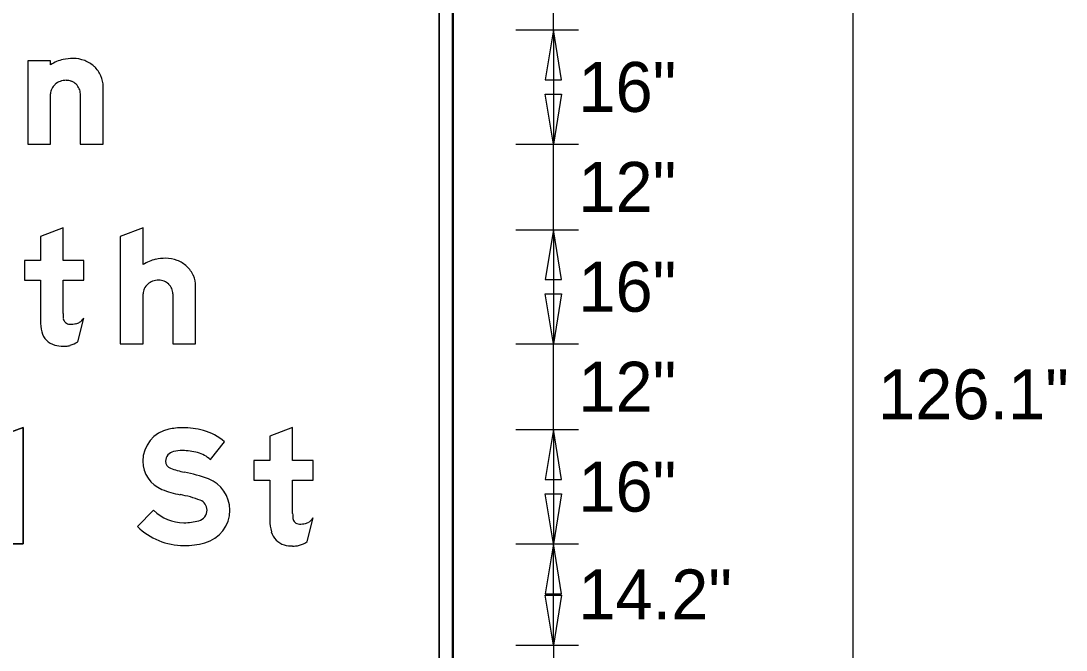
# Model space of a CAD drawing. Extents: x 2149961 to 2150220, y 145114 to 145240.
# Drawn here: x 2149993.88 to 2150006.08, y 145219.03 to 145226.37 of the extents above; entities that cross this region are included whole.
import ezdxf

# ---------------------------------------------------------------- set-up
doc = ezdxf.new("R2010")
doc.units = 0
for name, color, linetype in [('GSBWFILL', 7, 'Continuous'), ('GSCOLORFILL', 7, 'Continuous'), ('GSDIMS', 7, 'Continuous'), ('GSOUTLINE', 7, 'Continuous')]:
    doc.layers.add(name, color=color, linetype=linetype)

msp = doc.modelspace()

# ---------------------------------------------------------------- linework, layer by layer
at = {"layer": 'GSBWFILL'}
for p, q in [((2149998.763, 145232.262), (2149998.763, 145217.762)), ((2149998.93, 145217.762), (2149998.93, 145232.262)), ((2149994.572, 145225.522), (2149994.572, 145224.937)), ((2149994.542, 145222.628), (2149994.612, 145222.904)), ((2149997.222, 145220.295), (2149997.292, 145220.571))]:
    msp.add_line(p, q, dxfattribs=at)
for points in [[(2149994.226, 145225.862), (2149994.226, 145225.91), (2149993.959, 145225.91), (2149993.959, 145224.937), (2149994.226, 145224.937), (2149994.226, 145225.522)], [(2149994.572, 145224.937), (2149994.839, 145224.937), (2149994.839, 145225.609)], [(2149994.372, 145222.957), (2149994.372, 145223.347), (2149994.612, 145223.347), (2149994.612, 145223.577), (2149994.372, 145223.577), (2149994.372, 145223.96), (2149994.106, 145223.859), (2149994.106, 145223.577), (2149993.919, 145223.577), (2149993.919, 145223.347), (2149994.106, 145223.347), (2149994.106, 145222.876)], [(2149995.306, 145223.529), (2149995.306, 145223.96), (2149995.039, 145223.857), (2149995.039, 145222.604), (2149995.306, 145222.604), (2149995.306, 145223.188)], [(2149995.652, 145223.188), (2149995.652, 145222.604), (2149995.919, 145222.604), (2149995.919, 145223.276)], [(2149993.639, 145220.302), (2149993.639, 145220.27), (2149993.906, 145220.27), (2149993.906, 145221.627), (2149993.639, 145221.529), (2149993.639, 145221.212)], [(2149997.052, 145220.624), (2149997.052, 145221.014), (2149997.292, 145221.014), (2149997.292, 145221.244), (2149997.052, 145221.244), (2149997.052, 145221.627), (2149996.786, 145221.526), (2149996.786, 145221.244), (2149996.599, 145221.244), (2149996.599, 145221.014), (2149996.786, 145221.014), (2149996.786, 145220.543)], [(2149996.092, 145221.252), (2149996.257, 145221.462)], [(2149995.427, 145220.662), (2149995.239, 145220.473)]]:
    msp.add_lwpolyline(points, dxfattribs=at)
for centre, radius, start, end in [((2149994.483, 145225.457), 0.48, 103.4695, 122.4943), ((2149994.488, 145225.403), 0.533, 90, 102.6043), ((2149994.488, 145225.561), 0.375, 68.8636, 90), ((2149994.497, 145225.585), 0.35, 46.975, 68.8636), ((2149994.511, 145225.6), 0.33, 23.9317, 46.975), ((2149994.399, 145225.496), 0.183, 109.8074, 131.0076), ((2149994.408, 145225.471), 0.21, 90, 109.8074), ((2149994.408, 145225.512), 0.168, 68.0808, 90), ((2149994.41, 145225.517), 0.164, 45.8298, 68.0808), ((2149994.533, 145225.609), 0.306, 0, 23.9317), ((2149994.364, 145225.522), 0.139, 154.5283, 180), ((2149994.386, 145225.511), 0.162, 131.0076, 154.5283), ((2149994.413, 145225.52), 0.159, 23.0928, 45.8298), ((2149994.418, 145225.522), 0.155, 0, 23.0928), ((2149995.563, 145223.124), 0.48, 103.4695, 122.4943), ((2149995.568, 145223.07), 0.533, 90, 102.6043), ((2149995.568, 145223.228), 0.375, 68.8636, 90), ((2149995.577, 145223.252), 0.35, 46.975, 68.8636), ((2149995.591, 145223.266), 0.33, 23.9317, 46.975), ((2149995.479, 145223.162), 0.183, 109.8074, 131.0076), ((2149995.488, 145223.137), 0.21, 90, 109.8074), ((2149995.488, 145223.179), 0.168, 68.0808, 90), ((2149995.49, 145223.183), 0.164, 45.8298, 68.0808), ((2149995.613, 145223.276), 0.306, 0, 23.9317), ((2149995.444, 145223.188), 0.139, 154.5283, 180), ((2149995.466, 145223.178), 0.162, 131.0076, 154.5283), ((2149995.493, 145223.186), 0.159, 23.0928, 45.8298), ((2149995.498, 145223.188), 0.155, 0, 23.0928)]:
    msp.add_arc(centre, radius, start, end, dxfattribs=at)
for centre, major_axis, ratio, start_param, end_param in [((2149996.041, 145222.957), (0, 1.669), 0.99999, 1.570796, 1.606005), ((2149994.623, 145222.876), (0, 0.517), 0.99999, 1.570796, 1.830698), ((2149994.449, 145222.911), (0, 0.0767), 0.99999, 1.74085, 2.407828), ((2149994.451, 145222.914), (0, 0.0803), 0.99999, 2.407828, 3.141593), ((2149994.451, 145223.255), (0, 0.421), 0.99999, 3.141593, 3.310762), ((2149994.505, 145222.938), (0, 0.1), 0.99999, 3.310762, 3.756278), ((2149994.437, 145223.035), (0, 0.219), 0.99999, 3.756278, 4.071638), ((2149994.332, 145222.799), (0, 0.217), 0.99999, 1.830698, 2.869526), ((2149994.372, 145222.942), (0, 0.365), 0.99999, 2.869526, 3.141593), ((2149994.364, 145222.891), (0, 0.317), 0.99999, 3.427755, 3.738844), ((2149994.372, 145223.103), (0, 0.526), 0.99999, 3.141593, 3.205734), ((2149994.392, 145222.794), (0, 0.217), 0.99999, 3.205734, 3.427755), ((2149995.765, 145220.839), (0, 0.785), 0.999996, 0, 0.202758), ((2149995.765, 145220.661), (0, 0.963), 0.999996, 6.026234, 6.283185), ((2149995.684, 145221.234), (0, 0.382), 0.999996, 0.202758, 1.570796), ((2149995.855, 145221.001), (0, 0.611), 0.999996, 5.565152, 6.026234), ((2149995.684, 145221.234), (0, 0.115), 0.999996, 0.202758, 1.570796), ((2149995.765, 145220.839), (0, 0.519), 0.999996, 0, 0.202758), ((2149995.765, 145220.661), (0, 0.697), 0.999996, 6.026234, 6.283185), ((2149995.855, 145221.001), (0, 0.345), 0.999996, 5.523837, 6.026234), ((2149995.656, 145221.234), (0, 0.354), 0.999996, 1.570796, 2.761249), ((2149995.656, 145221.234), (0, 0.0872), 0.999996, 1.570796, 2.761249), ((2149995.947, 145221.961), (0, 0.87), 0.999996, 2.761249, 2.95744), ((2149995.49, 145219.51), (0, 1.623), 0.999996, 5.918637, 6.099033), ((2149995.93, 145220.664), (0, 0.388), 0.999996, 4.712389, 5.918637), ((2149995.947, 145221.961), (0, 1.137), 0.999996, 2.761249, 2.95744), ((2149995.49, 145219.51), (0, 1.357), 0.999996, 5.918637, 6.099033), ((2149995.93, 145220.664), (0, 0.122), 0.999996, 4.712389, 5.918637), ((2149995.782, 145221.02), (0, 0.504), 0.999996, 2.360607, 3.141593), ((2149995.923, 145220.664), (0, 0.129), 0.999996, 3.401517, 4.712389), ((2149995.923, 145220.664), (0, 0.396), 0.999996, 3.401517, 4.712389), ((2149995.782, 145221.194), (0, 0.678), 0.999996, 3.141593, 3.401517), ((2149997.303, 145220.543), (0, 0.517), 0.999994, 1.570796, 1.830698), ((2149998.721, 145220.624), (0, 1.669), 0.999994, 1.570796, 1.606005), ((2149997.129, 145220.578), (0, 0.0767), 0.999994, 1.74085, 2.407828), ((2149997.131, 145220.58), (0, 0.0803), 0.999994, 2.407828, 3.141593), ((2149997.185, 145220.605), (0, 0.1), 0.999994, 3.310762, 3.756278), ((2149997.117, 145220.702), (0, 0.219), 0.999994, 3.756278, 4.071638), ((2149995.782, 145221.02), (0, 0.771), 0.999996, 2.360607, 3.141593), ((2149997.012, 145220.466), (0, 0.217), 0.999994, 1.830698, 2.869526), ((2149997.131, 145220.921), (0, 0.421), 0.999994, 3.141593, 3.310762), ((2149995.782, 145221.194), (0, 0.945), 0.999996, 3.141593, 3.401517), ((2149997.044, 145220.557), (0, 0.317), 0.999994, 3.427755, 3.738844), ((2149997.052, 145220.609), (0, 0.365), 0.999994, 2.869526, 3.141593), ((2149997.052, 145220.769), (0, 0.526), 0.999994, 3.141593, 3.205734), ((2149997.072, 145220.461), (0, 0.217), 0.999994, 3.205734, 3.427755)]:
    msp.add_ellipse(centre, major_axis=major_axis, ratio=ratio, start_param=start_param, end_param=end_param, dxfattribs=at)
at = {"layer": 'GSCOLORFILL'}
for p, q in [((2149998.763, 145232.262), (2149998.763, 145217.762)), ((2149998.913, 145232.262), (2149998.913, 145217.762)), ((2149998.93, 145217.762), (2149998.93, 145232.262)), ((2149998.93, 145217.762), (2149998.93, 145232.262)), ((2149998.93, 145217.762), (2149998.93, 145232.262)), ((2149994.572, 145225.522), (2149994.572, 145224.937)), ((2149994.542, 145222.628), (2149994.612, 145222.904)), ((2149997.222, 145220.295), (2149997.292, 145220.571))]:
    msp.add_line(p, q, dxfattribs=at)
for points in [[(2149994.226, 145225.862), (2149994.226, 145225.91), (2149993.959, 145225.91), (2149993.959, 145224.937), (2149994.226, 145224.937), (2149994.226, 145225.522)], [(2149994.572, 145224.937), (2149994.839, 145224.937), (2149994.839, 145225.609)], [(2149994.372, 145222.957), (2149994.372, 145223.347), (2149994.612, 145223.347), (2149994.612, 145223.577), (2149994.372, 145223.577), (2149994.372, 145223.96), (2149994.106, 145223.859), (2149994.106, 145223.577), (2149993.919, 145223.577), (2149993.919, 145223.347), (2149994.106, 145223.347), (2149994.106, 145222.876)], [(2149995.306, 145223.529), (2149995.306, 145223.96), (2149995.039, 145223.857), (2149995.039, 145222.604), (2149995.306, 145222.604), (2149995.306, 145223.188)], [(2149995.652, 145223.188), (2149995.652, 145222.604), (2149995.919, 145222.604), (2149995.919, 145223.276)], [(2149993.639, 145220.302), (2149993.639, 145220.27), (2149993.906, 145220.27), (2149993.906, 145221.627), (2149993.639, 145221.529), (2149993.639, 145221.212)], [(2149997.052, 145220.624), (2149997.052, 145221.014), (2149997.292, 145221.014), (2149997.292, 145221.244), (2149997.052, 145221.244), (2149997.052, 145221.627), (2149996.786, 145221.526), (2149996.786, 145221.244), (2149996.599, 145221.244), (2149996.599, 145221.014), (2149996.786, 145221.014), (2149996.786, 145220.543)], [(2149996.092, 145221.252), (2149996.257, 145221.462)], [(2149995.427, 145220.662), (2149995.239, 145220.473)]]:
    msp.add_lwpolyline(points, dxfattribs=at)
for centre, radius, start, end in [((2149994.483, 145225.457), 0.48, 103.4695, 122.4943), ((2149994.488, 145225.403), 0.533, 90, 102.6043), ((2149994.488, 145225.561), 0.375, 68.8636, 90), ((2149994.497, 145225.585), 0.35, 46.975, 68.8636), ((2149994.511, 145225.6), 0.33, 23.9317, 46.975), ((2149994.399, 145225.496), 0.183, 109.8074, 131.0076), ((2149994.408, 145225.471), 0.21, 90, 109.8074), ((2149994.408, 145225.512), 0.168, 68.0808, 90), ((2149994.41, 145225.517), 0.164, 45.8298, 68.0808), ((2149994.533, 145225.609), 0.306, 0, 23.9317), ((2149994.364, 145225.522), 0.139, 154.5283, 180), ((2149994.386, 145225.511), 0.162, 131.0076, 154.5283), ((2149994.413, 145225.52), 0.159, 23.0928, 45.8298), ((2149994.418, 145225.522), 0.155, 0, 23.0928), ((2149995.563, 145223.124), 0.48, 103.4695, 122.4943), ((2149995.568, 145223.07), 0.533, 90, 102.6043), ((2149995.568, 145223.228), 0.375, 68.8636, 90), ((2149995.577, 145223.252), 0.35, 46.975, 68.8636), ((2149995.591, 145223.266), 0.33, 23.9317, 46.975), ((2149995.479, 145223.162), 0.183, 109.8074, 131.0076), ((2149995.488, 145223.137), 0.21, 90, 109.8074), ((2149995.488, 145223.179), 0.168, 68.0808, 90), ((2149995.49, 145223.183), 0.164, 45.8298, 68.0808), ((2149995.613, 145223.276), 0.306, 0, 23.9317), ((2149995.444, 145223.188), 0.139, 154.5283, 180), ((2149995.466, 145223.178), 0.162, 131.0076, 154.5283), ((2149995.493, 145223.186), 0.159, 23.0928, 45.8298), ((2149995.498, 145223.188), 0.155, 0, 23.0928)]:
    msp.add_arc(centre, radius, start, end, dxfattribs=at)
for centre, major_axis, ratio, start_param, end_param in [((2149996.041, 145222.957), (0, 1.669), 0.99999, 1.570796, 1.606005), ((2149994.623, 145222.876), (0, 0.517), 0.99999, 1.570796, 1.830698), ((2149994.449, 145222.911), (0, 0.0767), 0.99999, 1.74085, 2.407828), ((2149994.451, 145222.914), (0, 0.0803), 0.99999, 2.407828, 3.141593), ((2149994.451, 145223.255), (0, 0.421), 0.99999, 3.141593, 3.310762), ((2149994.505, 145222.938), (0, 0.1), 0.99999, 3.310762, 3.756278), ((2149994.437, 145223.035), (0, 0.219), 0.99999, 3.756278, 4.071638), ((2149994.332, 145222.799), (0, 0.217), 0.99999, 1.830698, 2.869526), ((2149994.372, 145222.942), (0, 0.365), 0.99999, 2.869526, 3.141593), ((2149994.364, 145222.891), (0, 0.317), 0.99999, 3.427755, 3.738844), ((2149994.372, 145223.103), (0, 0.526), 0.99999, 3.141593, 3.205734), ((2149994.392, 145222.794), (0, 0.217), 0.99999, 3.205734, 3.427755), ((2149995.765, 145220.839), (0, 0.785), 0.999996, 0, 0.202758), ((2149995.765, 145220.661), (0, 0.963), 0.999996, 6.026234, 6.283185), ((2149995.684, 145221.234), (0, 0.382), 0.999996, 0.202758, 1.570796), ((2149995.855, 145221.001), (0, 0.611), 0.999996, 5.565152, 6.026234), ((2149995.684, 145221.234), (0, 0.115), 0.999996, 0.202758, 1.570796), ((2149995.765, 145220.839), (0, 0.519), 0.999996, 0, 0.202758), ((2149995.765, 145220.661), (0, 0.697), 0.999996, 6.026234, 6.283185), ((2149995.855, 145221.001), (0, 0.345), 0.999996, 5.523837, 6.026234), ((2149995.656, 145221.234), (0, 0.354), 0.999996, 1.570796, 2.761249), ((2149995.656, 145221.234), (0, 0.0872), 0.999996, 1.570796, 2.761249), ((2149995.947, 145221.961), (0, 0.87), 0.999996, 2.761249, 2.95744), ((2149995.49, 145219.51), (0, 1.623), 0.999996, 5.918637, 6.099033), ((2149995.93, 145220.664), (0, 0.388), 0.999996, 4.712389, 5.918637), ((2149995.947, 145221.961), (0, 1.137), 0.999996, 2.761249, 2.95744), ((2149995.49, 145219.51), (0, 1.357), 0.999996, 5.918637, 6.099033), ((2149995.93, 145220.664), (0, 0.122), 0.999996, 4.712389, 5.918637), ((2149995.782, 145221.02), (0, 0.504), 0.999996, 2.360607, 3.141593), ((2149995.923, 145220.664), (0, 0.129), 0.999996, 3.401517, 4.712389), ((2149995.923, 145220.664), (0, 0.396), 0.999996, 3.401517, 4.712389), ((2149995.782, 145221.194), (0, 0.678), 0.999996, 3.141593, 3.401517), ((2149997.303, 145220.543), (0, 0.517), 0.999994, 1.570796, 1.830698), ((2149998.721, 145220.624), (0, 1.669), 0.999994, 1.570796, 1.606005), ((2149997.129, 145220.578), (0, 0.0767), 0.999994, 1.74085, 2.407828), ((2149997.131, 145220.58), (0, 0.0803), 0.999994, 2.407828, 3.141593), ((2149997.185, 145220.605), (0, 0.1), 0.999994, 3.310762, 3.756278), ((2149997.117, 145220.702), (0, 0.219), 0.999994, 3.756278, 4.071638), ((2149995.782, 145221.02), (0, 0.771), 0.999996, 2.360607, 3.141593), ((2149997.012, 145220.466), (0, 0.217), 0.999994, 1.830698, 2.869526), ((2149997.131, 145220.921), (0, 0.421), 0.999994, 3.141593, 3.310762), ((2149995.782, 145221.194), (0, 0.945), 0.999996, 3.141593, 3.401517), ((2149997.044, 145220.557), (0, 0.317), 0.999994, 3.427755, 3.738844), ((2149997.052, 145220.609), (0, 0.365), 0.999994, 2.869526, 3.141593), ((2149997.052, 145220.769), (0, 0.526), 0.999994, 3.141593, 3.205734), ((2149997.072, 145220.461), (0, 0.217), 0.999994, 3.205734, 3.427755)]:
    msp.add_ellipse(centre, major_axis=major_axis, ratio=ratio, start_param=start_param, end_param=end_param, dxfattribs=at)
at = {"layer": 'GSDIMS'}
for p, q in [((2150000.096, 145226.27), (2150000.096, 145227.27)), ((2150003.596, 145216.762), (2150003.596, 145227.27)), ((2149999.659, 145226.27), (2150000.388, 145226.27)), ((2149999.659, 145226.27), (2150000.388, 145226.27)), ((2150000.096, 145226.27), (2150000.096, 145224.937)), ((2149999.659, 145224.937), (2150000.388, 145224.937)), ((2149999.659, 145224.937), (2150000.388, 145224.937)), ((2150000.096, 145223.937), (2150000.096, 145224.937)), ((2149999.659, 145223.937), (2150000.388, 145223.937)), ((2149999.659, 145223.937), (2150000.388, 145223.937)), ((2150000.096, 145223.937), (2150000.096, 145222.604)), ((2149999.659, 145222.604), (2150000.388, 145222.604)), ((2149999.659, 145222.604), (2150000.388, 145222.604)), ((2150000.096, 145221.604), (2150000.096, 145222.604)), ((2149999.659, 145221.604), (2150000.388, 145221.604)), ((2149999.659, 145221.604), (2150000.388, 145221.604)), ((2150000.096, 145221.604), (2150000.096, 145220.27)), ((2149999.659, 145220.27), (2150000.388, 145220.27)), ((2149999.659, 145220.27), (2150000.388, 145220.27)), ((2150000.096, 145219.087), (2150000.096, 145220.27)), ((2149999.659, 145219.087), (2150000.388, 145219.087)), ((2149999.659, 145219.087), (2150000.388, 145219.087)), ((2150000.096, 145219.087), (2150000.096, 145218.254))]:
    msp.add_line(p, q, dxfattribs=at)
for points in [[(2150000.096, 145226.27), (2149999.999, 145225.687), (2150000.193, 145225.687)], [(2150000.096, 145224.937), (2149999.999, 145225.52), (2150000.193, 145225.52)], [(2150000.096, 145223.937), (2149999.999, 145223.354), (2150000.193, 145223.354)], [(2150000.096, 145222.604), (2149999.999, 145223.187), (2150000.193, 145223.187)], [(2150000.096, 145221.604), (2149999.999, 145221.02), (2150000.193, 145221.02)], [(2150000.096, 145220.27), (2149999.999, 145220.854), (2150000.193, 145220.854)], [(2150000.096, 145220.27), (2149999.999, 145219.687), (2150000.193, 145219.687)], [(2150000.096, 145219.087), (2149999.999, 145219.67), (2150000.193, 145219.67)]]:
    msp.add_lwpolyline(points, close=True, dxfattribs=at)
at = {"layer": 'GSOUTLINE'}
for p, q in [((2149998.763, 145217.762), (2149998.763, 145232.262)), ((2149998.93, 145217.762), (2149998.93, 145232.262)), ((2149994.572, 145225.522), (2149994.572, 145224.937)), ((2149994.542, 145222.628), (2149994.612, 145222.904)), ((2149997.222, 145220.295), (2149997.292, 145220.571))]:
    msp.add_line(p, q, dxfattribs=at)
for points in [[(2149994.226, 145225.862), (2149994.226, 145225.91), (2149993.959, 145225.91), (2149993.959, 145224.937), (2149994.226, 145224.937), (2149994.226, 145225.522)], [(2149994.572, 145224.937), (2149994.839, 145224.937), (2149994.839, 145225.609)], [(2149994.372, 145222.957), (2149994.372, 145223.347), (2149994.612, 145223.347), (2149994.612, 145223.577), (2149994.372, 145223.577), (2149994.372, 145223.96), (2149994.106, 145223.859), (2149994.106, 145223.577), (2149993.919, 145223.577), (2149993.919, 145223.347), (2149994.106, 145223.347), (2149994.106, 145222.876)], [(2149995.306, 145223.529), (2149995.306, 145223.96), (2149995.039, 145223.857), (2149995.039, 145222.604), (2149995.306, 145222.604), (2149995.306, 145223.188)], [(2149995.652, 145223.188), (2149995.652, 145222.604), (2149995.919, 145222.604), (2149995.919, 145223.276)], [(2149993.639, 145221.212), (2149993.639, 145221.529), (2149993.906, 145221.627), (2149993.906, 145220.27), (2149993.639, 145220.27), (2149993.639, 145220.302)], [(2149997.052, 145220.624), (2149997.052, 145221.014), (2149997.292, 145221.014), (2149997.292, 145221.244), (2149997.052, 145221.244), (2149997.052, 145221.627), (2149996.786, 145221.526), (2149996.786, 145221.244), (2149996.599, 145221.244), (2149996.599, 145221.014), (2149996.786, 145221.014), (2149996.786, 145220.543)], [(2149996.092, 145221.252), (2149996.257, 145221.462)], [(2149995.427, 145220.662), (2149995.239, 145220.473)]]:
    msp.add_lwpolyline(points, dxfattribs=at)
for centre, radius, start, end in [((2149994.483, 145225.457), 0.48, 103.4695, 122.4943), ((2149994.488, 145225.403), 0.533, 90, 102.6043), ((2149994.488, 145225.561), 0.375, 68.8636, 90), ((2149994.497, 145225.585), 0.35, 46.975, 68.8636), ((2149994.511, 145225.6), 0.33, 23.9317, 46.975), ((2149994.399, 145225.496), 0.183, 109.8074, 131.0076), ((2149994.408, 145225.471), 0.21, 90, 109.8074), ((2149994.408, 145225.512), 0.168, 68.0808, 90), ((2149994.41, 145225.517), 0.164, 45.8298, 68.0808), ((2149994.533, 145225.609), 0.306, 0, 23.9317), ((2149994.364, 145225.522), 0.139, 154.5283, 180), ((2149994.386, 145225.511), 0.162, 131.0076, 154.5283), ((2149994.413, 145225.52), 0.159, 23.0928, 45.8298), ((2149994.418, 145225.522), 0.155, 0, 23.0928), ((2149995.563, 145223.124), 0.48, 103.4695, 122.4943), ((2149995.568, 145223.07), 0.533, 90, 102.6043), ((2149995.568, 145223.228), 0.375, 68.8636, 90), ((2149995.577, 145223.252), 0.35, 46.975, 68.8636), ((2149995.591, 145223.266), 0.33, 23.9317, 46.975), ((2149995.479, 145223.162), 0.183, 109.8074, 131.0076), ((2149995.488, 145223.137), 0.21, 90, 109.8074), ((2149995.488, 145223.179), 0.168, 68.0808, 90), ((2149995.49, 145223.183), 0.164, 45.8298, 68.0808), ((2149995.613, 145223.276), 0.306, 0, 23.9317), ((2149995.444, 145223.188), 0.139, 154.5283, 180), ((2149995.466, 145223.178), 0.162, 131.0076, 154.5283), ((2149995.493, 145223.186), 0.159, 23.0928, 45.8298), ((2149995.498, 145223.188), 0.155, 0, 23.0928)]:
    msp.add_arc(centre, radius, start, end, dxfattribs=at)
for centre, major_axis, ratio, start_param, end_param in [((2149996.041, 145222.957), (0, 1.669), 0.99999, 1.570796, 1.606005), ((2149994.623, 145222.876), (0, 0.517), 0.99999, 1.570796, 1.830698), ((2149994.449, 145222.911), (0, 0.0767), 0.99999, 1.74085, 2.407828), ((2149994.451, 145222.914), (0, 0.0803), 0.99999, 2.407828, 3.141593), ((2149994.451, 145223.255), (0, 0.421), 0.99999, 3.141593, 3.310762), ((2149994.505, 145222.938), (0, 0.1), 0.99999, 3.310762, 3.756278), ((2149994.437, 145223.035), (0, 0.219), 0.99999, 3.756278, 4.071638), ((2149994.332, 145222.799), (0, 0.217), 0.99999, 1.830698, 2.869526), ((2149994.372, 145222.942), (0, 0.365), 0.99999, 2.869526, 3.141593), ((2149994.364, 145222.891), (0, 0.317), 0.99999, 3.427755, 3.738844), ((2149994.372, 145223.103), (0, 0.526), 0.99999, 3.141593, 3.205734), ((2149994.392, 145222.794), (0, 0.217), 0.99999, 3.205734, 3.427755), ((2149995.765, 145220.839), (0, 0.785), 0.999996, 0, 0.202758), ((2149995.765, 145220.661), (0, 0.963), 0.999996, 6.026234, 6.283185), ((2149995.684, 145221.234), (0, 0.382), 0.999996, 0.202758, 1.570796), ((2149995.855, 145221.001), (0, 0.611), 0.999996, 5.565152, 6.026234), ((2149995.684, 145221.234), (0, 0.115), 0.999996, 0.202758, 1.570796), ((2149995.765, 145220.839), (0, 0.519), 0.999996, 0, 0.202758), ((2149995.765, 145220.661), (0, 0.697), 0.999996, 6.026234, 6.283185), ((2149995.855, 145221.001), (0, 0.345), 0.999996, 5.523837, 6.026234), ((2149995.656, 145221.234), (0, 0.354), 0.999996, 1.570796, 2.761249), ((2149995.656, 145221.234), (0, 0.0872), 0.999996, 1.570796, 2.761249), ((2149995.947, 145221.961), (0, 0.87), 0.999996, 2.761249, 2.95744), ((2149995.49, 145219.51), (0, 1.623), 0.999996, 5.918637, 6.099033), ((2149995.93, 145220.664), (0, 0.388), 0.999996, 4.712389, 5.918637), ((2149995.947, 145221.961), (0, 1.137), 0.999996, 2.761249, 2.95744), ((2149995.49, 145219.51), (0, 1.357), 0.999996, 5.918637, 6.099033), ((2149995.93, 145220.664), (0, 0.122), 0.999996, 4.712389, 5.918637), ((2149995.782, 145221.02), (0, 0.504), 0.999996, 2.360607, 3.141593), ((2149995.923, 145220.664), (0, 0.129), 0.999996, 3.401517, 4.712389), ((2149995.923, 145220.664), (0, 0.396), 0.999996, 3.401517, 4.712389), ((2149995.782, 145221.194), (0, 0.678), 0.999996, 3.141593, 3.401517), ((2149997.303, 145220.543), (0, 0.517), 0.999994, 1.570796, 1.830698), ((2149998.721, 145220.624), (0, 1.669), 0.999994, 1.570796, 1.606005), ((2149997.129, 145220.578), (0, 0.0767), 0.999994, 1.74085, 2.407828), ((2149997.131, 145220.58), (0, 0.0803), 0.999994, 2.407828, 3.141593), ((2149997.185, 145220.605), (0, 0.1), 0.999994, 3.310762, 3.756278), ((2149997.117, 145220.702), (0, 0.219), 0.999994, 3.756278, 4.071638), ((2149995.782, 145221.02), (0, 0.771), 0.999996, 2.360607, 3.141593), ((2149997.012, 145220.466), (0, 0.217), 0.999994, 1.830698, 2.869526), ((2149997.131, 145220.921), (0, 0.421), 0.999994, 3.141593, 3.310762), ((2149995.782, 145221.194), (0, 0.945), 0.999996, 3.141593, 3.401517), ((2149997.044, 145220.557), (0, 0.317), 0.999994, 3.427755, 3.738844), ((2149997.052, 145220.609), (0, 0.365), 0.999994, 2.869526, 3.141593), ((2149997.052, 145220.769), (0, 0.526), 0.999994, 3.141593, 3.205734), ((2149997.072, 145220.461), (0, 0.217), 0.999994, 3.205734, 3.427755)]:
    msp.add_ellipse(centre, major_axis=major_axis, ratio=ratio, start_param=start_param, end_param=end_param, dxfattribs=at)

# ---------------------------------------------------------------- texts
at = {"layer": 'GSDIMS'}
for s, p in [('16"', (2150000.388, 145225.312)), ('12"', (2150000.388, 145224.145)), ('16"', (2150000.388, 145222.979)), ('12"', (2150000.388, 145221.812)), ('126.1"', (2150003.888, 145221.724)), ('16"', (2150000.388, 145220.645)), ('14.2"', (2150000.388, 145219.387))]:
    msp.add_text(s, height=0.5833, dxfattribs=at).set_placement(p)

doc.saveas('drawing.dxf')
